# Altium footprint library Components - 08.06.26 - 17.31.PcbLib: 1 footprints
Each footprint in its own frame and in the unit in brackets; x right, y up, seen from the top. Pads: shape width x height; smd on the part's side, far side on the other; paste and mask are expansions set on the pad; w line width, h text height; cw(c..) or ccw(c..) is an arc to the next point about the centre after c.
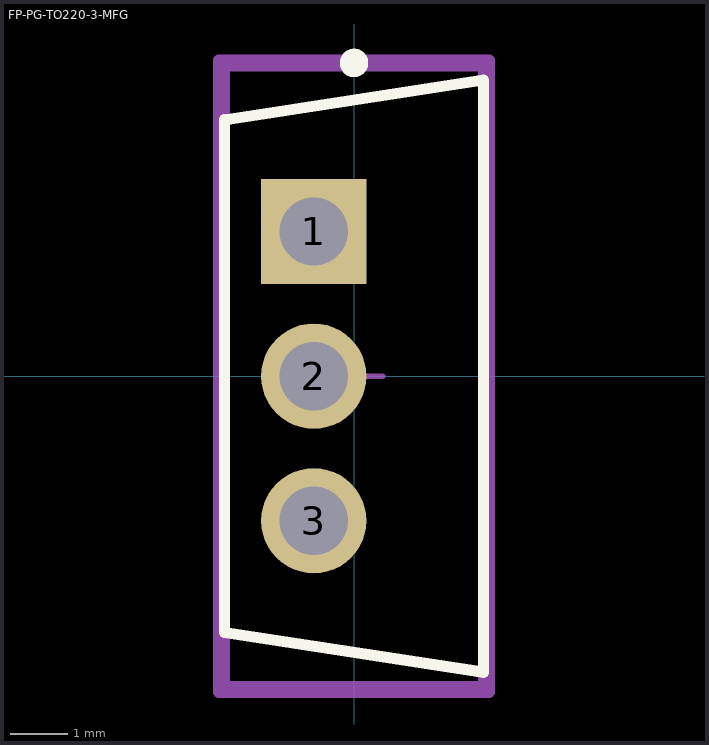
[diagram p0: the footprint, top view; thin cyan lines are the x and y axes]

## FP-PG-TO220-3-MFG [mm]
pads (3):
  rect 1.85x1.85 hole 1.2 paste-2539.97 mask+0: 1(-0.705,2.54)
  round 1.85 hole 1.2 paste-2539.97 mask+0: 2(-0.705,0) 3(-0.705,-2.54)
Top Overlay:
  circle w0.25: c0,5.5 r0.125
  lines w0.2: -2.275,-4.5 -2.275,4.5 2.275,5.2 2.275,-5.2 -2.275,-4.5
Top Assembly:
  lines w0.2: -2.375,-5.55 -2.375,5.55 2.375,5.55 2.375,-5.55 -2.375,-5.55
  text ".Designator" at 0,-0.001 h1
Top 3D Body:
  lines w0.2: -2.275,-5.45 -2.275,5.45 2.275,5.45 2.275,-5.45 -2.275,-5.45
Top Courtyard:
  lines w0.2: -2.375,-5.55 -2.375,5.55 2.375,5.55 2.375,-5.55 -2.375,-5.55
Top Component Center:
  lines w0.1: -0.5,0 0.5,0 ; 0,-0.5 0,0.5
3D body "Trans_Infineon_IRL2505PBF_eec.STEP": height 0.25, standoff 0, extent -2.375,-5.55 2.375,5.55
